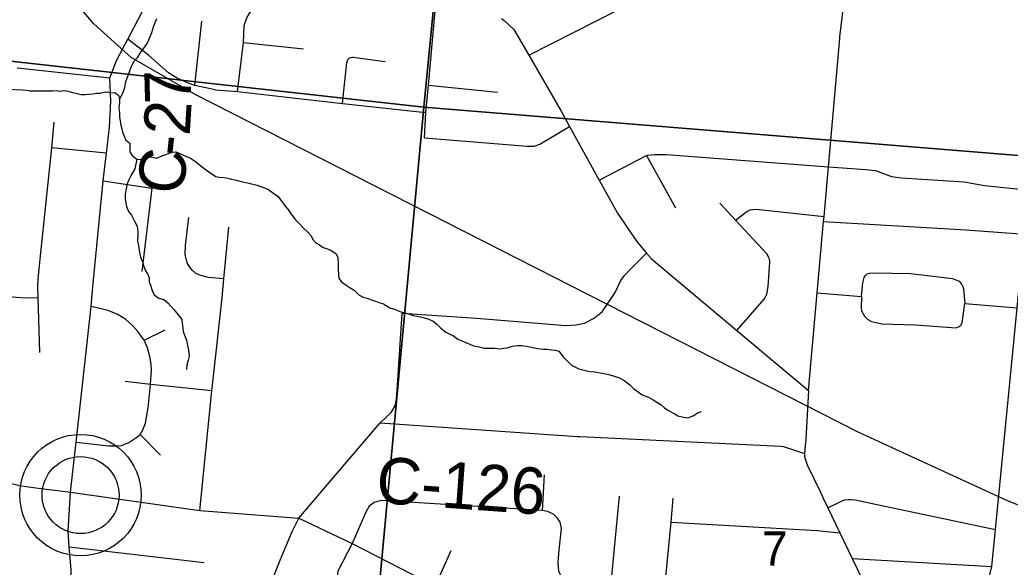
# Model space of a CAD drawing. Extents: x 0 to 34, y -2 to 22.
# Drawn here: x 4.85 to 6.064, y 18.207 to 18.879 of the extents above; entities that cross this region are included whole.
import ezdxf

# ---------------------------------------------------------------- set-up
doc = ezdxf.new("R2010")
doc.units = 0
for name, color, linetype in [('GM_X_City_Street', 7, 'Continuous'), ('GM_X_County_Road', 7, 'Continuous'), ('GM_X_County_Road_Text', 7, 'Continuous'), ('GM_X_Minor_River', 7, 'Continuous'), ('GM_X_Rail_Line', 7, 'Continuous'), ('GM_X_Section', 7, 'Continuous'), ('GM_X_Section_Text', 7, 'Continuous'), ('GM_X_State_Route', 7, 'Continuous'), ('GM_X_Township_Road', 7, 'Continuous'), ('GM_X_Unincorporated', 7, 'Continuous'), ('GM_X_Unincorporated_Location', 7, 'Continuous')]:
    doc.layers.add(name, color=color, linetype=linetype)

msp = doc.modelspace()

# ---------------------------------------------------------------- linework, layer by layer
at = {"layer": 'GM_X_City_Street'}
for p, q in [((5.1241, 18.8509), (5.1976, 18.843)), ((5.3507, 18.7985), (5.4353, 18.7897)), ((5.6182, 18.7122), (5.6537, 18.6479)), ((5.8274, 18.5438), (5.8818, 18.5394)), ((6.0082, 18.5307), (6.0727, 18.5254)), ((5.8274, 18.2525), (5.8551, 18.2497)), ((5.8704, 18.218), (6.0415, 18.2083))]:
    msp.add_line(p, q, dxfattribs=at)
for points in [[(5.4737, 18.8351), (5.638, 18.919), (5.7445, 18.9753)], [(5.1169, 18.7907), (5.1241, 18.8509), (5.125, 18.8714), (5.1281, 18.8808), (5.131, 18.886), (5.1342, 18.8902), (5.1451, 18.8998), (5.1548, 18.9041), (5.1581, 18.9055), (5.1626, 18.9066), (5.1674, 18.9069), (5.1801, 18.906), (5.3592, 18.8894)], [(5.2454, 18.7758), (5.2509, 18.8262), (5.2516, 18.8284), (5.2525, 18.8303), (5.2536, 18.8314), (5.2551, 18.8322), (5.2569, 18.8327), (5.2587, 18.8328), (5.2976, 18.8275)], [(5.0895, 18.7926), (5.1169, 18.7907), (5.2454, 18.7758), (5.3475, 18.7649)], [(5.3458, 18.7337), (5.4718, 18.7236), (5.4802, 18.7236), (5.4875, 18.726), (5.5239, 18.7477)], [(5.5601, 18.6821), (5.6182, 18.7122), (5.6192, 18.7127), (5.628, 18.7136), (5.6428, 18.7132), (5.8412, 18.6983), (5.8869, 18.6949), (5.899, 18.6937), (5.9185, 18.6863), (5.9303, 18.6848), (6.0076, 18.6799), (6.0325, 18.6753), (6.0876, 18.6697), (6.1162, 18.6667), (6.1387, 18.6672), (6.1627, 18.6699), (6.1798, 18.6713), (6.1919, 18.6698), (6.2153, 18.6653), (6.2288, 18.6584)], [(5.7287, 18.4978), (5.7624, 18.5359), (5.7637, 18.5382), (5.7656, 18.5423), (5.7674, 18.5514), (5.7695, 18.5813), (5.7693, 18.5832), (5.7688, 18.5852), (5.7678, 18.5876), (5.766, 18.5913), (5.7272, 18.633), (5.7079, 18.6538)], [(5.7272, 18.633), (5.741, 18.6434), (5.7452, 18.6455), (5.7525, 18.6464), (5.8358, 18.6375)], [(5.8352, 18.6314), (6.01, 18.6209), (6.0817, 18.6159), (6.2989, 18.6009)], [(5.8818, 18.5394), (5.8834, 18.5561), (5.8851, 18.5625), (5.8857, 18.5637), (5.8868, 18.5653), (5.8886, 18.567), (5.8914, 18.568), (5.8959, 18.5683), (5.9417, 18.5674), (5.9934, 18.5612), (5.9973, 18.5599), (6.0014, 18.5581), (6.0047, 18.5542), (6.0058, 18.5516), (6.0068, 18.5485), (6.0073, 18.5442), (6.0082, 18.5307)], [(5.8818, 18.5394), (5.8811, 18.5258), (5.8815, 18.5217), (5.8853, 18.515), (5.8894, 18.5109), (5.8939, 18.5087), (5.9067, 18.5057), (5.948, 18.5046), (5.9976, 18.501), (6.0016, 18.5024), (6.0035, 18.5042), (6.005, 18.5069), (6.0082, 18.5307)], [(5.8404, 18.2803), (5.8563, 18.2881), (5.8608, 18.2899), (5.8653, 18.2904), (5.8688, 18.2906), (5.8738, 18.2898), (5.9044, 18.2836), (5.9878, 18.2659), (6.046, 18.2538)]]:
    msp.add_lwpolyline(points, dxfattribs=at)
at = {"layer": 'GM_X_County_Road'}
msp.add_line((5.3124, 18.424), (5.3185, 18.5187), dxfattribs=at)
for points in [[(5.8551, 18.8555), (5.8553, 18.8576), (5.8648, 18.9389), (5.8728, 19.0034), (5.876, 19.0597), (5.8847, 19.138), (5.8947, 19.2279), (5.9011, 19.2954), (5.9014, 19.2974)], [(5.3458, 18.7337), (5.3475, 18.7649), (5.3507, 18.7985), (5.3592, 18.8894), (5.3632, 18.9241), (5.3642, 18.9306), (5.3657, 18.9369), (5.3701, 18.9424), (5.3765, 18.947)], [(4.9603, 18.8074), (4.9689, 18.8296), (4.9823, 18.8547), (4.9848, 18.8593), (5.0154, 18.9184)], [(5.8168, 18.424), (5.8274, 18.5438), (5.8352, 18.6314), (5.8358, 18.6375), (5.8412, 18.6983), (5.8551, 18.8555)], [(6.0016, 18.0431), (6.0019, 18.0445), (6.021, 18.1411), (6.0254, 18.1559), (6.0314, 18.1723), (6.0371, 18.1896), (6.0415, 18.2083), (6.046, 18.2538), (6.0727, 18.5254), (6.0817, 18.6159), (6.0876, 18.6697), (6.1081, 18.8523)], [(4.8467, 18.8198), (4.8508, 18.8193), (4.9603, 18.8074)], [(4.9058, 18.0895), (4.914, 18.1636), (4.9129, 18.2041), (4.9103, 18.2323), (4.9092, 18.2511), (4.912, 18.2992), (4.919, 18.3609), (4.9373, 18.5269), (4.9392, 18.5513), (4.9522, 18.681), (4.956, 18.7149), (4.96, 18.7468), (4.9616, 18.7789), (4.9603, 18.8074)], [(5.3185, 18.5187), (5.4098, 18.5128), (5.5194, 18.5037), (5.5318, 18.5045), (5.5423, 18.5067), (5.5533, 18.5123), (5.5639, 18.5205), (5.5799, 18.5441), (5.5867, 18.5588), (5.5913, 18.5652), (5.5985, 18.5729), (5.6183, 18.5923)], [(5.2918, 18.3843), (5.305, 18.3972), (5.3106, 18.4061), (5.3118, 18.4137), (5.3124, 18.424)], [(5.1995, 17.7504), (5.2081, 17.8122), (5.2137, 17.863), (5.2158, 17.884), (5.216, 17.9002), (5.2124, 17.92), (5.2081, 17.9372), (5.1901, 17.9956), (5.1796, 18.033), (5.167, 18.0759), (5.1529, 18.1255), (5.1513, 18.1344), (5.1502, 18.1437), (5.1505, 18.1536), (5.1514, 18.1624), (5.1532, 18.1709), (5.1565, 18.1821), (5.1626, 18.1996), (5.1689, 18.2162), (5.1837, 18.2512), (5.192, 18.2677), (5.2341, 18.3169), (5.2918, 18.3843)], [(5.2918, 18.3843), (5.5336, 18.3677), (5.5366, 18.3675)], [(5.5366, 18.3675), (5.7829, 18.3556), (5.786, 18.3552), (5.812, 18.3467)], [(4.8069, 18.3317), (4.8175, 18.3221), (4.8379, 18.3106), (4.8493, 18.3077), (4.8696, 18.3046), (4.912, 18.2992), (5.0707, 18.2768), (5.192, 18.2677)], [(5.192, 18.2677), (5.2571, 18.2366), (5.359, 18.1842), (5.4743, 18.1391), (5.6103, 18.0859), (5.6567, 18.0677), (5.6692, 18.064), (5.685, 18.0612)]]:
    msp.add_lwpolyline(points, dxfattribs=at)
at = {"layer": 'GM_X_Minor_River'}
for points in [[(4.9721, 18.7811), (4.9757, 18.7879), (4.9785, 18.7951), (4.9799, 18.803), (4.9819, 18.8083), (4.9836, 18.8124), (4.986, 18.8196), (4.9897, 18.8275), (4.9944, 18.8327), (4.9975, 18.8376), (5.0011, 18.8424), (5.0059, 18.8495), (5.0079, 18.854), (5.0099, 18.8589), (5.0115, 18.8631), (5.014, 18.871), (5.0177, 18.88)], [(4.8347, 18.7934), (4.8533, 18.7928), (4.8583, 18.7923), (4.8624, 18.7914), (4.8689, 18.7913), (4.878, 18.7914), (4.8837, 18.7916), (4.8902, 18.7914), (4.8944, 18.7917), (4.8993, 18.7912), (4.9043, 18.7918), (4.9092, 18.7909), (4.9145, 18.7896), (4.9186, 18.7887), (4.9251, 18.787), (4.93, 18.7869), (4.9346, 18.7875), (4.9392, 18.7878), (4.9437, 18.7884), (4.9479, 18.7887), (4.9533, 18.7897), (4.9575, 18.7903), (4.9616, 18.789), (4.9662, 18.7893), (4.9707, 18.7861), (4.9721, 18.7811), (4.9719, 18.7766), (4.9714, 18.7709), (4.972, 18.7644), (4.9722, 18.759), (4.9729, 18.7545), (4.9735, 18.7495), (4.9749, 18.7449), (4.9759, 18.7407), (4.9777, 18.7357), (4.9798, 18.731), (4.9847, 18.7271), (4.9849, 18.7225), (4.9848, 18.7168), (4.9877, 18.7121), (4.9933, 18.7078), (5.0001, 18.7072), (5.0066, 18.7097), (5.0108, 18.7107), (5.0173, 18.709), (5.025, 18.7122), (5.0299, 18.714), (5.0361, 18.7161), (5.041, 18.7167), (5.0591, 18.709), (5.0651, 18.705), (5.0718, 18.6995), (5.077, 18.6956), (5.0856, 18.6892), (5.09, 18.6864), (5.0942, 18.6856), (5.1003, 18.6854), (5.1048, 18.6845), (5.109, 18.6832), (5.1135, 18.6823), (5.1211, 18.6802), (5.129, 18.6785), (5.1354, 18.6772), (5.1407, 18.6759), (5.1486, 18.673), (5.1539, 18.6709), (5.1595, 18.667), (5.1666, 18.6618), (5.1706, 18.656), (5.1743, 18.6513), (5.1798, 18.6447), (5.1827, 18.6404), (5.1879, 18.6334), (5.1923, 18.6287), (5.1975, 18.6229), (5.2027, 18.6185), (5.2071, 18.6135), (5.2089, 18.6092), (5.2129, 18.6049), (5.2171, 18.6025), (5.2219, 18.5993), (5.2272, 18.5977), (5.2317, 18.5956), (5.2373, 18.592), (5.2399, 18.5874), (5.24, 18.5783), (5.2402, 18.5722), (5.2404, 18.5664), (5.2411, 18.5619), (5.244, 18.5576), (5.2488, 18.554), (5.2537, 18.5508), (5.2597, 18.5469), (5.2656, 18.5414)], [(4.9933, 18.7078), (4.991, 18.6957), (4.9863, 18.6882), (4.9834, 18.6822), (4.9814, 18.6773), (4.9801, 18.6712), (4.9792, 18.6648), (4.979, 18.6583), (4.9807, 18.6495), (4.9832, 18.6437), (4.9868, 18.639), (4.9904, 18.6317), (4.9937, 18.6255), (4.9947, 18.619), (4.9945, 18.6144), (4.9943, 18.6068), (4.9953, 18.6019), (4.9966, 18.5931), (4.9976, 18.5877), (5.0005, 18.5811), (5.0019, 18.5762), (5.0036, 18.5715), (5.0062, 18.5669), (5.0083, 18.5623), (5.0086, 18.5573), (5.01, 18.5531), (5.0121, 18.5465), (5.0146, 18.5415), (5.0202, 18.5372), (5.0266, 18.5355), (5.0315, 18.5315), (5.0385, 18.5233), (5.044, 18.5167), (5.0484, 18.5109), (5.049, 18.5067), (5.0496, 18.5006), (5.0503, 18.4963), (5.0517, 18.4917), (5.0542, 18.4856), (5.0555, 18.4791), (5.0565, 18.4733), (5.0574, 18.4661), (5.0562, 18.4611), (5.0545, 18.4555), (5.0543, 18.4498)], [(5.2656, 18.5414), (5.2701, 18.539), (5.2776, 18.5365), (5.2818, 18.5348), (5.2859, 18.5336), (5.2901, 18.5319), (5.2957, 18.5302), (5.3036, 18.5254), (5.3104, 18.5234), (5.3156, 18.5209), (5.3277, 18.5175), (5.3322, 18.5159), (5.3409, 18.5145), (5.347, 18.5128), (5.3511, 18.5116), (5.3564, 18.5091), (5.3612, 18.5052), (5.366, 18.5005), (5.372, 18.4954), (5.3769, 18.4933), (5.3817, 18.4909), (5.387, 18.4869), (5.4016, 18.4808), (5.4061, 18.4788), (5.4129, 18.4775), (5.4186, 18.4761), (5.4323, 18.4758), (5.438, 18.4752), (5.4433, 18.4758), (5.4475, 18.4765), (5.454, 18.4782), (5.4601, 18.4792), (5.4651, 18.4794), (5.473, 18.4781), (5.4802, 18.4763), (5.4848, 18.4754), (5.492, 18.4749), (5.4965, 18.4747), (5.5015, 18.4738), (5.506, 18.4737), (5.5105, 18.4721), (5.5161, 18.4654), (5.526, 18.4552), (5.5302, 18.4532), (5.5351, 18.4508), (5.5434, 18.4487), (5.5487, 18.4474), (5.5547, 18.4468), (5.5589, 18.4463), (5.5638, 18.4454), (5.5718, 18.4437), (5.5849, 18.4395), (5.5906, 18.4363), (5.5976, 18.4308), (5.6021, 18.4265), (5.6062, 18.4237), (5.6129, 18.4189), (5.6204, 18.4157), (5.6264, 18.4125), (5.6309, 18.4097), (5.6358, 18.4069), (5.6402, 18.4029), (5.6443, 18.3998), (5.6522, 18.3957), (5.6567, 18.3929), (5.6635, 18.3912), (5.6688, 18.3907), (5.6761, 18.3932), (5.6808, 18.3965), (5.6854, 18.3982)]]:
    msp.add_lwpolyline(points, dxfattribs=at)
at = {"layer": 'GM_X_Rail_Line'}
msp.add_lwpolyline([(6.3781, 18.1955), (6.3337, 18.2177), (6.2546, 18.2399), (6.1073, 18.27), (6.0598, 18.289), (5.8778, 18.373), (5.0656, 18.7866), (4.9864, 18.8325), (4.9405, 18.8737), (4.8962, 18.926), (4.8471, 19.0021), (4.7558, 19.2114), (4.6999, 19.3545), (4.657, 19.4903)], dxfattribs=at)
at = {"layer": 'GM_X_Section'}
for points in [[(5.4475, 19.8207), (5.4431, 19.7776), (5.3451, 18.7715), (4.3356, 18.8839), (4.4338, 19.8873), (4.7992, 19.8486), (4.8002, 19.892)], [(5.4431, 19.7776), (6.443, 19.687), (6.3407, 18.6907), (5.3451, 18.7715)], [(4.3356, 18.8839), (5.3451, 18.7715), (5.25, 17.7471), (4.2197, 17.8557)], [(6.3407, 18.6907), (6.241, 17.6971), (5.25, 17.7471), (5.3451, 18.7715)]]:
    msp.add_lwpolyline(points, close=True, dxfattribs=at)
at = {"layer": 'GM_X_State_Route'}
for points in [[(5.4403, 18.8801), (5.4435, 18.8777), (5.4554, 18.8667), (5.4737, 18.8351), (5.5134, 18.7667), (5.5239, 18.7477), (5.5601, 18.6821), (5.5825, 18.6414), (5.5997, 18.616), (5.6074, 18.6053), (5.6183, 18.5923), (5.6241, 18.5853), (5.7287, 18.4978), (5.8168, 18.424), (5.8134, 18.3641), (5.8123, 18.3523), (5.812, 18.3467), (5.8118, 18.3428), (5.815, 18.3331), (5.8313, 18.2993)], [(5.8313, 18.2993), (5.8344, 18.2927), (5.8404, 18.2803), (5.8551, 18.2497), (5.8704, 18.218), (5.8832, 18.1912)]]:
    msp.add_lwpolyline(points, dxfattribs=at)
at = {"layer": 'GM_X_Township_Road'}
for p, q in [((5.0645, 18.7978), (5.0731, 18.877)), ((4.956, 18.7149), (4.8889, 18.7215)), ((4.9522, 18.681), (5.0117, 18.6721)), ((5.0117, 18.6721), (4.9994, 18.5698)), ((5.0023, 18.4856), (5.028, 18.4984)), ((5.0101, 18.4313), (4.9792, 18.4351)), ((5.0852, 18.4237), (5.0101, 18.4313)), ((4.9972, 18.3701), (5.0225, 18.3448)), ((5.4906, 18.2768), (5.4929, 18.3205)), ((5.5728, 18.1695), (5.5852, 18.2943)), ((5.6483, 18.2627), (5.8274, 18.2525)), ((4.9103, 18.2323), (5.0759, 18.2133)), ((5.359, 18.1842), (5.3787, 18.2277))]:
    msp.add_line(p, q, dxfattribs=at)
for points in [[(5.0895, 18.7926), (5.0645, 18.7978), (5.0562, 18.8007), (5.0429, 18.807), (5.0322, 18.8137), (5.0078, 18.8351), (4.9823, 18.8547)], [(4.8914, 18.7529), (4.8889, 18.7215), (4.875, 18.5892)], [(5.0999, 18.5609), (5.0807, 18.5626), (5.0706, 18.5654), (5.0653, 18.5681), (5.0612, 18.5715), (5.0594, 18.5736), (5.0574, 18.5765), (5.055, 18.5805), (5.0527, 18.5908), (5.0528, 18.6019), (5.057, 18.6361)], [(5.0707, 18.2768), (5.0852, 18.4237), (5.0872, 18.4416), (5.0978, 18.5375), (5.0999, 18.5609), (5.1059, 18.6242)], [(4.875, 18.5892), (4.8733, 18.5729), (4.8718, 18.5608), (4.8715, 18.5509), (4.8719, 18.5382), (4.874, 18.4705)], [(4.7429, 18.5003), (4.7993, 18.531), (4.8126, 18.5382), (4.8175, 18.5397), (4.8281, 18.5402), (4.8457, 18.5386), (4.8559, 18.5376), (4.8719, 18.5382)], [(4.919, 18.3609), (4.9591, 18.3563), (4.9673, 18.3563), (4.9744, 18.3568), (4.9835, 18.3602), (4.992, 18.366), (4.9972, 18.3701), (5.0008, 18.3759), (5.0039, 18.3838), (5.0044, 18.387), (5.007, 18.4029), (5.0101, 18.4313), (5.0113, 18.4488), (5.0107, 18.4562), (5.0091, 18.4659), (5.0062, 18.4765), (5.0023, 18.4856), (4.9945, 18.4964), (4.9881, 18.5037), (4.9798, 18.511), (4.9693, 18.5178), (4.9578, 18.5223), (4.9481, 18.5247), (4.9373, 18.5269)], [(5.6331, 18.147), (5.5728, 18.1695), (5.5272, 18.1857), (5.5195, 18.1902), (5.5138, 18.1951), (5.5105, 18.2027), (5.5098, 18.2126), (5.5107, 18.2244), (5.514, 18.255), (5.5122, 18.2628), (5.5089, 18.2677), (5.5041, 18.2723), (5.4968, 18.2756), (5.4906, 18.2768), (5.2927, 18.2891), (5.2844, 18.2867), (5.2781, 18.2824), (5.274, 18.2749), (5.2571, 18.2366), (5.2399, 18.2026), (5.2384, 18.1933), (5.2407, 18.1449), (5.2446, 18.0329)], [(5.6103, 18.0859), (5.6331, 18.147), (5.6343, 18.1503), (5.6367, 18.1558), (5.6387, 18.1619), (5.6483, 18.2627), (5.6509, 18.292)]]:
    msp.add_lwpolyline(points, dxfattribs=at)
at = {"layer": 'GM_X_Unincorporated'}
for radius in [0.0744, 0.0472]:
    msp.add_circle((4.9243, 18.2958), radius, dxfattribs=at)
at = {"layer": 'GM_X_Unincorporated_Location'}
msp.add_line((4.9243, 18.2958), (4.9243, 18.2958), dxfattribs=at)

# ---------------------------------------------------------------- texts
at = {"layer": 'GM_X_County_Road_Text'}
for s, height, rotation, p in [('7', 0.0568, 91.5631, (5.0603, 18.7761)), ('2', 0.0568, 86.3745, (5.058, 18.7356)), ('-', 0.0568, 83.9783, (5.0553, 18.7098)), ('C', 0.0568, 83.4934, (5.0499, 18.6629)), ('C-126', 0.05682, 355.8754, (5.2856, 18.2865))]:
    msp.add_text(s, height=height, rotation=rotation, dxfattribs=at).set_placement(p)
at = {"layer": 'GM_X_Section_Text'}
msp.add_text('7', height=0.0419, rotation=0, dxfattribs=at).set_placement((5.7598, 18.2093))

doc.saveas('drawing.dxf')
